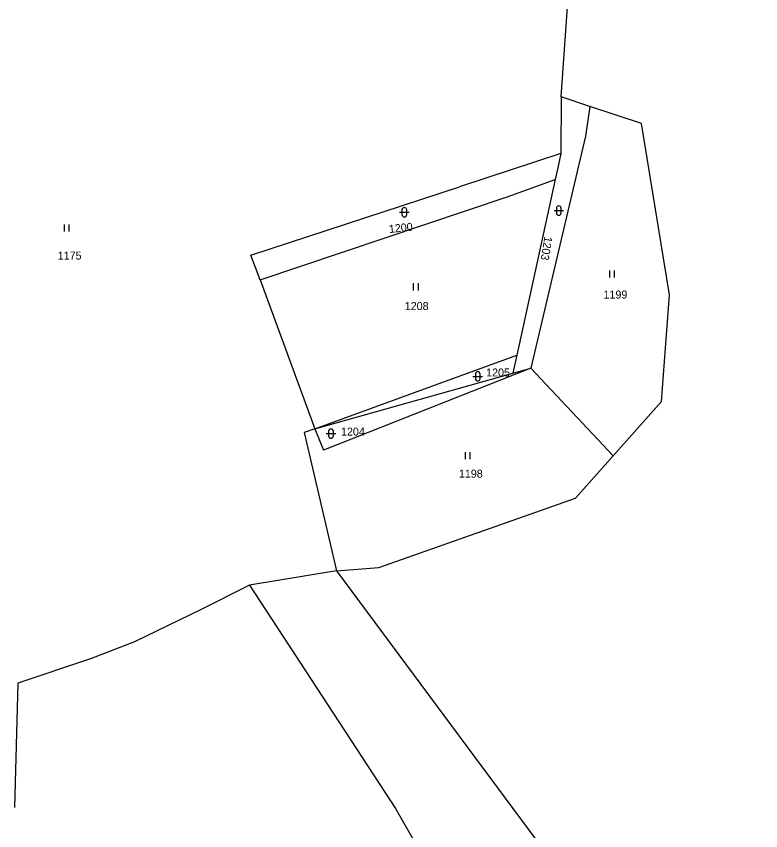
# Model space of a CAD drawing. Extents: x -744132 to -742433, y -984679 to -982287.
# Drawn here: x -742676.3 to -742518.3, y -983370.4 to -983197.5 of the extents above; entities that cross this region are included whole.
import ezdxf

# ---------------------------------------------------------------- set-up
doc = ezdxf.new("R2010")
doc.units = 0
doc.header["$LTSCALE"] = 0.68
doc.layers.add('1', color=7, linetype='Continuous', lineweight=25)
doc.layers.add('3', color=7, linetype='Continuous', lineweight=25)
doc.layers.add('2', color=7, linetype='Continuous')

msp = doc.modelspace()

# ---------------------------------------------------------------- linework, layer by layer
at = {"layer": '1'}
for p, q in [((-742560.62, -983214.63), (-742558.82, -983189.2)), ((-742560.62, -983214.63), (-742560.73, -983226.6)), ((-742554.53, -983216.65), (-742560.62, -983214.63)), ((-742554.53, -983216.65), (-742555.48, -983222.93)), ((-742543.58, -983220.28), (-742554.53, -983216.65)), ((-742537.65, -983256.66), (-742543.58, -983220.28)), ((-742555.48, -983222.93), (-742567.11, -983272.21)), ((-742560.73, -983226.6), (-742582.19, -983233.74)), ((-742560.73, -983226.6), (-742561.34, -983229.69)), ((-742561.34, -983229.69), (-742561.89, -983232.18)), ((-742571.86, -983235.73), (-742561.89, -983232.18)), ((-742561.89, -983232.18), (-742570.06, -983269.42)), ((-742626.49, -983248.22), (-742582.19, -983233.74)), ((-742624.55, -983253.47), (-742571.86, -983235.73)), ((-742624.55, -983253.47), (-742626.49, -983248.22)), ((-742624.55, -983253.47), (-742612.9, -983285.08)), ((-742539.32, -983279.25), (-742537.65, -983256.66)), ((-742612.9, -983285.08), (-742570.06, -983269.42)), ((-742570.06, -983269.42), (-742570.9, -983273.27)), ((-742567.11, -983272.21), (-742611.11, -983289.62)), ((-742570.9, -983273.27), (-742567.11, -983272.21)), ((-742567.11, -983272.21), (-742549.59, -983290.78)), ((-742612.9, -983285.08), (-742570.9, -983273.27)), ((-742549.59, -983290.78), (-742539.32, -983279.25)), ((-742612.9, -983285.08), (-742615.18, -983285.85)), ((-742612.9, -983285.08), (-742611.11, -983289.62)), ((-742615.18, -983285.85), (-742608.33, -983315.24)), ((-742557.59, -983299.77), (-742549.59, -983290.78)), ((-742599.34, -983314.49), (-742557.59, -983299.77)), ((-742608.33, -983315.24), (-742599.34, -983314.49)), ((-742608.33, -983315.24), (-742626.77, -983318.26)), ((-742608.33, -983315.24), (-742518.29, -983436.49)), ((-742626.77, -983318.26), (-742637.04, -983323.4)), ((-742626.77, -983318.26), (-742595.81, -983365.68)), ((-742637.04, -983323.4), (-742651.19, -983330.28)), ((-742651.19, -983330.28), (-742660.57, -983333.86)), ((-742660.57, -983333.86), (-742675.94, -983339.08)), ((-742675.94, -983339.08), (-742676.68, -983365.44)), ((-742595.81, -983365.68), (-742582.42, -983389.06))]:
    msp.add_line(p, q, dxfattribs=at)
at = {"layer": '3'}
for p, q in [((-742561.651, -983238.241), (-742561.651, -983239.242)), ((-742560.649, -983239.242), (-742560.649, -983238.241)), ((-742594.931, -983239.101), (-742592.929, -983239.101)), ((-742594.431, -983238.601), (-742594.431, -983239.602)), ((-742593.429, -983239.602), (-742593.429, -983238.601)), ((-742562.151, -983238.741), (-742560.149, -983238.741)), ((-742666.051, -983243.22), (-742666.051, -983241.72)), ((-742665.05, -983243.22), (-742665.05, -983241.72)), ((-742550.321, -983252.96), (-742550.321, -983251.46)), ((-742549.32, -983252.96), (-742549.32, -983251.46)), ((-742591.961, -983255.69), (-742591.961, -983254.19)), ((-742590.96, -983255.69), (-742590.96, -983254.19)), ((-742579.361, -983273.941), (-742577.359, -983273.941)), ((-742578.861, -983273.441), (-742578.861, -983274.442)), ((-742577.859, -983274.442), (-742577.859, -983273.441)), ((-742610.501, -983286.091), (-742608.499, -983286.091)), ((-742610.001, -983285.591), (-742610.001, -983286.592)), ((-742608.999, -983286.592), (-742608.999, -983285.591)), ((-742580.961, -983291.52), (-742580.961, -983290.02)), ((-742579.96, -983291.52), (-742579.96, -983290.02))]:
    msp.add_line(p, q, dxfattribs=at)
for centre, start, end in [((-742593.93, -983238.6009), 0, 180), ((-742561.15, -983238.2409), 0, 180), ((-742593.93, -983239.6009), 180, 359.98789), ((-742561.15, -983239.2409), 180, 359.98789), ((-742578.36, -983273.4409), 0, 180), ((-742578.36, -983274.4409), 180, 359.98789), ((-742609.5, -983285.5909), 0, 180), ((-742609.5, -983286.5909), 180, 359.98789)]:
    msp.add_arc(centre, 0.5, start, end, dxfattribs=at)

# ---------------------------------------------------------------- texts
at = {"layer": '2'}
for s, rotation, p in [('1200', 6, (-742597.115, -983243.522)), ('1203', 261, (-742564.179, -983244.163))]:
    msp.add_text(s, height=1.7, rotation=rotation, dxfattribs=at).set_placement(p)
for s, p in [('1175', (-742667.5, -983249.155)), ('1199', (-742551.66, -983257.425)), ('1208', (-742593.84, -983259.865)), ('1205', (-742576.57, -983273.965)), ('1204', (-742607.37, -983286.515)), ('1198', (-742582.35, -983295.445))]:
    msp.add_text(s, height=1.7, dxfattribs=at).set_placement(p)

doc.saveas('drawing.dxf')
